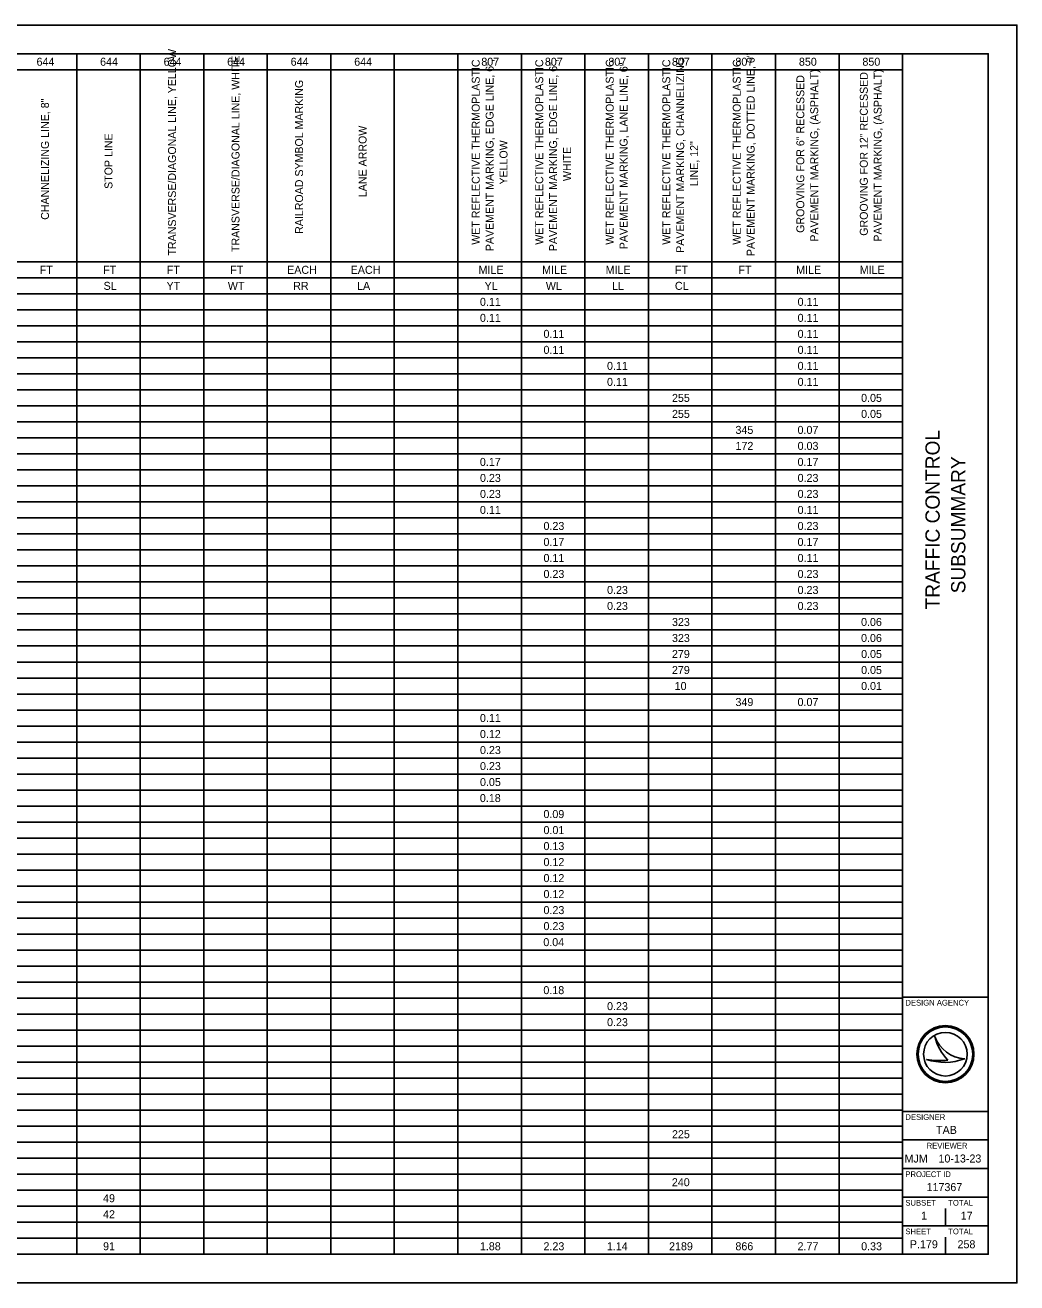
# Model space of a CAD drawing. Extents: x 0 to 34, y 0 to 22.
# Drawn here: x 16.65 to 34, y 0 to 22 of the extents above; entities that cross this region are included whole.
import ezdxf

# ---------------------------------------------------------------- set-up
doc = ezdxf.new("R2010")
doc.units = 0
for name, color, linetype in [('Default', 7, 'Continuous'), ('SH_Border', 7, 'Continuous'), ('SH_Cut_Line', 7, 'Continuous'), ('SH_Data', 7, 'Continuous')]:
    doc.layers.add(name, color=color, linetype=linetype)

msp = doc.modelspace()

# ---------------------------------------------------------------- linework, layer by layer
at = {"layer": 'Default'}
for p, q in [((1.5, 21.5), (32, 21.5)), ((17.551, 21.5), (17.551, 0.5)), ((18.662, 21.5), (18.662, 0.5)), ((19.774, 21.5), (19.774, 0.5)), ((20.885, 21.5), (20.885, 0.5)), ((21.997, 21.5), (21.997, 0.5)), ((23.108, 21.5), (23.108, 0.5)), ((24.22, 21.5), (24.22, 0.5)), ((25.331, 21.5), (25.331, 0.5)), ((26.443, 21.5), (26.443, 0.5)), ((27.554, 21.5), (27.554, 0.5)), ((28.666, 21.5), (28.666, 0.5)), ((29.777, 21.5), (29.777, 0.5)), ((30.889, 21.5), (30.889, 0.5)), ((32, 21.5), (32, 0.5)), ((8.659, 21.22), (32, 21.22)), ((8.659, 17.86), (32, 17.86)), ((1.5, 17.58), (32, 17.58)), ((1.5, 17.3), (32, 17.3)), ((1.5, 17.02), (32, 17.02)), ((1.5, 16.74), (32, 16.74)), ((1.5, 16.46), (32, 16.46)), ((1.5, 16.18), (32, 16.18)), ((1.5, 15.9), (32, 15.9)), ((1.5, 15.62), (32, 15.62)), ((1.5, 15.34), (32, 15.34)), ((1.5, 15.06), (32, 15.06)), ((1.5, 14.78), (32, 14.78)), ((1.5, 14.5), (32, 14.5)), ((1.5, 14.22), (32, 14.22)), ((1.5, 13.94), (32, 13.94)), ((1.5, 13.66), (32, 13.66)), ((1.5, 13.38), (32, 13.38)), ((1.5, 13.1), (32, 13.1)), ((1.5, 12.82), (32, 12.82)), ((1.5, 12.54), (32, 12.54)), ((1.5, 12.26), (32, 12.26)), ((1.5, 11.98), (32, 11.98)), ((1.5, 11.7), (32, 11.7)), ((1.5, 11.42), (32, 11.42)), ((1.5, 11.14), (32, 11.14)), ((1.5, 10.86), (32, 10.86)), ((1.5, 10.58), (32, 10.58)), ((1.5, 10.3), (32, 10.3)), ((1.5, 10.02), (32, 10.02)), ((1.5, 9.74), (32, 9.74)), ((1.5, 9.46), (32, 9.46)), ((1.5, 9.18), (32, 9.18)), ((1.5, 8.9), (32, 8.9)), ((1.5, 8.62), (32, 8.62)), ((1.5, 8.34), (32, 8.34)), ((1.5, 8.06), (32, 8.06)), ((1.5, 7.78), (32, 7.78)), ((1.5, 7.5), (32, 7.5)), ((1.5, 7.22), (32, 7.22)), ((1.5, 6.94), (32, 6.94)), ((1.5, 6.66), (32, 6.66)), ((1.5, 6.38), (32, 6.38)), ((1.5, 6.1), (32, 6.1)), ((1.5, 5.82), (32, 5.82)), ((1.5, 5.54), (32, 5.54)), ((1.5, 5.26), (32, 5.26)), ((1.5, 4.98), (32, 4.98)), ((1.5, 4.7), (32, 4.7)), ((1.5, 4.42), (32, 4.42)), ((1.5, 4.14), (32, 4.14)), ((1.5, 3.86), (32, 3.86)), ((1.5, 3.58), (32, 3.58)), ((1.5, 3.3), (32, 3.3)), ((1.5, 3.02), (32, 3.02)), ((1.5, 2.74), (32, 2.74)), ((1.5, 2.46), (32, 2.46)), ((1.5, 2.18), (32, 2.18)), ((1.5, 1.9), (32, 1.9)), ((1.5, 1.62), (32, 1.62)), ((1.5, 1.34), (32, 1.34)), ((1.5, 1.06), (32, 1.06)), ((1.5, 0.78), (32, 0.78)), ((1.5, 0.5), (32, 0.5))]:
    msp.add_line(p, q, dxfattribs=at)
at = {"layer": 'SH_Border'}
for p, q in [((32, 0.5), (32, 21.5)), ((32, 5), (33.5, 5)), ((32, 3), (33.5, 3)), ((32, 2.5), (33.5, 2.5)), ((32, 2), (33.5, 2)), ((32, 1.5), (33.5, 1.5)), ((32, 1), (33.5, 1))]:
    msp.add_line(p, q, dxfattribs=at)
msp.add_lwpolyline([(1.5, 21.5), (33.5, 21.5), (33.5, 0.5), (1.5, 0.5)], close=True, dxfattribs=at)
at = {"layer": 'SH_Cut_Line'}
msp.add_lwpolyline([(0, 0), (34, 0), (34, 22), (0, 22)], close=True, dxfattribs=at)
at = {"layer": 'SH_Data'}
for p, q in [((32.567, 4.31), (32.567, 4.31)), ((32.75, 4), (32.75, 4)), ((32.417, 3.91), (32.417, 3.91)), ((33.087, 3.919), (33.087, 3.919)), ((32.75, 1), (32.75, 1.3)), ((32.375, 0.675), (32.375, 0.675)), ((32.75, 0.5), (32.75, 0.8))]:
    msp.add_line(p, q, dxfattribs=at)
for radius in [0.5, 0.477, 0.477, 0.382]:
    msp.add_circle((32.75, 4), radius, dxfattribs=at)
for centre, radius, start, end in [((33.116, 4.498), 0.58, 198.9257, 198.9319), ((33.347, 4.47), 0.796, 191.6379, 191.6421), ((33.116, 4.498), 0.58, 198.9319, 267.1657), ((33.347, 4.47), 0.796, 191.6421, 226.0947), ((32.739, 4.87), 1.013, 251.4576, 290.0832), ((32.648, 5.154), 1.266, 259.4964, 259.4995), ((32.739, 4.87), 1.013, 251.4527, 251.4576), ((32.648, 5.154), 1.266, 259.4995, 276.6672)]:
    msp.add_arc(centre, radius, start, end, dxfattribs=at)

# ---------------------------------------------------------------- texts
at = {"layer": 'Default'}
for s, height, p in [('TRANSVERSE/DIAGONAL LINE, YELLOW', 0.13893, (19.288, 17.97)), ('TRANSVERSE/DIAGONAL LINE, WHITE', 0.13893, (20.399, 18.031)), ('WET REFLECTIVE THERMOPLASTIC ', 0.13893, (24.602, 18.159)), ('PAVEMENT MARKING, EDGE LINE, 6", ', 0.13893, (24.845, 18.046)), ('WET REFLECTIVE THERMOPLASTIC ', 0.13893, (25.713, 18.159)), ('PAVEMENT MARKING, EDGE LINE, 6", ', 0.13893, (25.956, 18.046)), ('WET REFLECTIVE THERMOPLASTIC ', 0.13893, (26.946, 18.159)), ('WET REFLECTIVE THERMOPLASTIC ', 0.13893, (27.936, 18.159)), ('PAVEMENT MARKING, CHANNELIZING ', 0.13893, (28.179, 18.017)), ('WET REFLECTIVE THERMOPLASTIC ', 0.13893, (29.169, 18.159)), ('PAVEMENT MARKING, DOTTED LINE, 6"', 0.13893, (29.412, 17.96)), ('PAVEMENT MARKING, LANE LINE, 6"', 0.13893, (27.189, 18.08)), ('PAVEMENT MARKING, (ASPHALT)', 0.13893, (30.524, 18.213)), ('GROOVING FOR 12" RECESSED ', 0.13893, (31.392, 18.316)), ('PAVEMENT MARKING, (ASPHALT)', 0.13893, (31.635, 18.213)), ('RAILROAD SYMBOL MARKING', 0.13893, (21.511, 18.349)), ('GROOVING FOR 6" RECESSED ', 0.13893, (30.281, 18.367)), ('CHANNELIZING LINE, 8"', 0.13893, (17.065, 18.595)), ('LANE ARROW', 0.1389, (22.622, 18.992)), ('STOP LINE', 0.1389, (18.176, 19.136)), ('YELLOW', 0.1389, (25.088, 19.212)), ('WHITE', 0.1389, (26.2, 19.273)), ('LINE, 12"', 0.1389, (28.422, 19.181))]:
    msp.add_text(s, height=height, rotation=90, dxfattribs=at).set_placement(p)
for s, p in [('644', (16.848, 21.29)), ('644', (17.96, 21.29)), ('644', (19.071, 21.29)), ('644', (20.183, 21.29)), ('644', (21.294, 21.29)), ('644', (22.406, 21.29)), ('807', (24.63, 21.29)), ('807', (25.742, 21.29)), ('807', (26.853, 21.29)), ('807', (27.965, 21.29)), ('807', (29.076, 21.29)), ('850', (30.187, 21.29)), ('850', (31.298, 21.29)), ('FT', (16.903, 17.65)), ('FT', (18.014, 17.65)), ('FT', (19.126, 17.65)), ('FT', (20.237, 17.65)), ('EACH', (21.232, 17.65)), ('EACH', (22.344, 17.65)), ('MILE', (24.582, 17.65)), ('MILE', (25.694, 17.65)), ('MILE', (26.805, 17.65)), ('FT', (28.017, 17.65)), ('FT', (29.129, 17.65)), ('MILE', (30.139, 17.65)), ('MILE', (31.251, 17.65)), ('SL', (18.021, 17.37)), ('YT', (19.123, 17.37)), ('WT', (20.195, 17.37)), ('RR', (21.338, 17.37)), ('LA', (22.456, 17.37)), ('YL', (24.687, 17.37)), ('WL', (25.759, 17.37)), ('LL', (26.916, 17.37)), ('CL', (28.017, 17.37)), ('0.11', (24.606, 17.09)), ('0.11', (30.164, 17.09)), ('0.11', (24.606, 16.81)), ('0.11', (30.164, 16.81)), ('0.11', (25.718, 16.53)), ('0.11', (30.164, 16.53)), ('0.11', (25.718, 16.25)), ('0.11', (30.164, 16.25)), ('0.11', (26.829, 15.97)), ('0.11', (30.164, 15.97)), ('0.11', (26.829, 15.69)), ('0.11', (30.164, 15.69)), ('255', (27.966, 15.41)), ('0.05', (31.275, 15.41)), ('255', (27.966, 15.13)), ('0.05', (31.275, 15.13)), ('345', (29.077, 14.85)), ('0.07', (30.163, 14.85)), ('172', (29.077, 14.57)), ('0.03', (30.164, 14.57)), ('0.17', (24.605, 14.29)), ('0.17', (30.163, 14.29)), ('0.23', (24.607, 14.01)), ('0.23', (30.164, 14.01)), ('0.23', (24.607, 13.73)), ('0.23', (30.164, 13.73)), ('0.11', (24.606, 13.45)), ('0.11', (30.164, 13.45)), ('0.23', (25.718, 13.17)), ('0.23', (30.164, 13.17)), ('0.17', (25.717, 12.89)), ('0.17', (30.163, 12.89)), ('0.11', (25.718, 12.61)), ('0.11', (30.164, 12.61)), ('0.23', (25.718, 12.33)), ('0.23', (30.164, 12.33)), ('0.23', (26.83, 12.05)), ('0.23', (30.164, 12.05)), ('0.23', (26.83, 11.77)), ('0.23', (30.164, 11.77)), ('323', (27.966, 11.49)), ('0.06', (31.274, 11.49)), ('323', (27.966, 11.21)), ('0.06', (31.274, 11.21)), ('279', (27.965, 10.93)), ('0.05', (31.275, 10.93)), ('279', (27.965, 10.65)), ('0.05', (31.275, 10.65)), ('10', (28.013, 10.37)), ('0.01', (31.275, 10.37)), ('349', (29.077, 10.09)), ('0.07', (30.163, 10.09)), ('0.11', (24.606, 9.81)), ('0.12', (24.606, 9.53)), ('0.23', (24.607, 9.25)), ('0.23', (24.607, 8.97)), ('0.05', (24.607, 8.69)), ('0.18', (24.605, 8.41)), ('0.09', (25.717, 8.13)), ('0.01', (25.718, 7.85)), ('0.13', (25.718, 7.57)), ('0.12', (25.718, 7.29)), ('0.12', (25.718, 7.01)), ('0.12', (25.718, 6.73)), ('0.23', (25.718, 6.45)), ('0.23', (25.718, 6.17)), ('0.04', (25.715, 5.89)), ('0.18', (25.716, 5.05)), ('0.23', (26.83, 4.77)), ('0.23', (26.83, 4.49)), ('225', (27.966, 2.53)), ('240', (27.964, 1.69)), ('49', (18.012, 1.41)), ('42', (18.012, 1.13)), ('91', (18.012, 0.57)), ('1.88', (24.605, 0.57)), ('2.23', (25.718, 0.57)), ('1.14', (26.827, 0.57)), ('2189', (27.915, 0.57)), ('866', (29.076, 0.57)), ('2.77', (30.163, 0.57)), ('0.33', (31.276, 0.57))]:
    msp.add_text(s, height=0.14, dxfattribs=at).set_placement(p)
at = {"layer": 'SH_Data'}
for s, p in [('TRAFFIC CONTROL', (32.65, 11.78)), ('SUBSUMMARY', (33.1, 12.061))]:
    msp.add_text(s, height=0.25, rotation=90, dxfattribs=at).set_placement(p)
for s, height, p in [('DESIGN AGENCY', 0.1, (32.05, 4.85)), ('DESIGNER', 0.1, (32.05, 2.85)), ('TAB', 0.14, (32.586, 2.605)), ('REVIEWER', 0.1, (32.422, 2.35)), ('MJM', 0.14, (32.035, 2.105)), ('10-13-23', 0.14, (32.629, 2.105)), ('PROJECT ID', 0.1, (32.05, 1.85)), ('117367', 0.14, (32.42, 1.605)), ('SUBSET', 0.1, (32.05, 1.35)), ('TOTAL', 0.1, (32.8, 1.35)), ('1', 0.14, (32.325, 1.105)), ('17', 0.14, (33.018, 1.105)), ('SHEET', 0.1, (32.05, 0.85)), ('TOTAL', 0.1, (32.8, 0.85)), ('P.179', 0.14, (32.128, 0.605)), ('258', 0.14, (32.962, 0.605))]:
    msp.add_text(s, height=height, dxfattribs=at).set_placement(p)

doc.saveas('drawing.dxf')
